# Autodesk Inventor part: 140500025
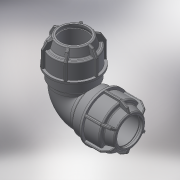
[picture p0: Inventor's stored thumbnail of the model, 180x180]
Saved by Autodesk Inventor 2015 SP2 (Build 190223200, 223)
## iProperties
Created: 2017-08
Part Number: 140500025
Material: Generic
Description: PLASSON L.14 90° ELBOW (SILVER) 25-25
Document SubType Name: Modeling
Designer: KIM
Density: 1 g/cm^3
Appearance: Default
Author: KIM
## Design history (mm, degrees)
derived "140500.ipt"
feature "Solid1::140500.ipt"
tag "TaggingFeature1"
body "Solid1"
other parameters: "d1" = 25, "d2" = 47, "d4" = 15 deg, "d5" = 31.02, "d6" = 10.2366, "d16" = 25.5, "d17" = 2.35, "d24" = 2.35, "d25" = 45, "d26" = 37.5, "d27" = 2.35, "d28" = 135 deg, "d29" = 1.41, "d31" = 1.25, "d46" = 150 deg, "d49" = 2.5, "d50" = 0, "d58" = 0.75, "d61" = 360 deg, "d63" = 22.5, "d80" = 36, "d81" = 2, "d84" = 2.35, "d112" = 62, "d113" = 2.48, "d115" = 90 deg, "d_" = 25, "A_" = 62, "l_" = 47
